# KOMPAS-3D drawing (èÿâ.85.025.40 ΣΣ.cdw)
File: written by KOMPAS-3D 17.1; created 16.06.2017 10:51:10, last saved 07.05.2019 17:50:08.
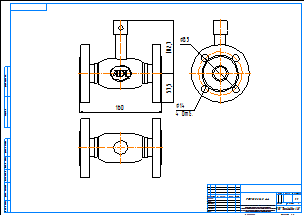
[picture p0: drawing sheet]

Sheet 1: A2, landscape

Title block, sheet 1: name: КШГ.85.025.40 фф; material: Внимание! Данный продукт является объектом авторского права ООО «Торговый Дом АДЛ». / Запрещается изменение, копирование, распространение / (в том числе путем копирования на другие сайты и ресурсы в Интернете) / или любое иное использование информации и объектов без предварительного / согласия правообладателя (ООО «Торговый Дом АДЛ»).; scale: 1:1; sheets: 1; organisation: ООО "Торговый дом АДЛ"; sheet format: A2; stored path: C:\Users\tra\Desktop\2д чертежи\Шаровые краны БИВАЛ\КШ_Бивал_серия_82_85\KOMPAS 2D\КШГ.85.025.40 фф.cdw

Views: Спереди 1, Проекционный вид 2, Проекционный вид 3
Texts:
  Klimkovich
  ADL
Dimensions and other numbers on the sheet: 160; 102,7; 57,5; 85; 14; 4 Отв.; 1:1; 1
